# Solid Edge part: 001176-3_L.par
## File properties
Last saved by: morva
Revision: 82
Accuracy: 0.990
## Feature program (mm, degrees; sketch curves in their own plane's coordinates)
body "unnamed Body 1"
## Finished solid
Body 1: solid body, 48 faces, 136 edges, 88 vertices.
  Faces by surface: cylinder 26, plane 14, spline 8
  Edges by curve: line 64, circle 48, curve on surface 24
Bounding box of the edges (mm; curved faces can reach further): 16.806 x 13.858 x 20.530, from (527.4879, 404.498, -82.5475) to (544.2943, 418.3564, -62.0175).
Cylindrical faces by radius (mm): R0.7366 x3, R1 x1, R1.5 x4, R1.517 x2, R2.2366 x3, R3 x2, R3.5 x3, R3.75 x3, R6 x5
Planar faces by outward normal: oblique 14
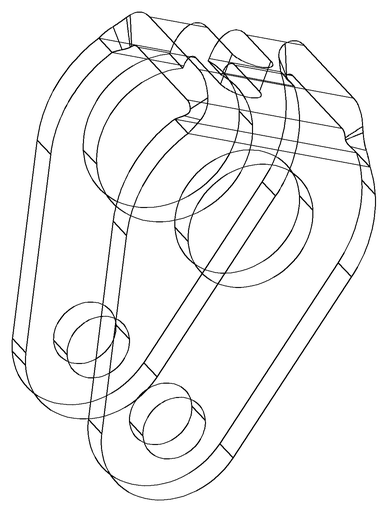
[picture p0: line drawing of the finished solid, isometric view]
